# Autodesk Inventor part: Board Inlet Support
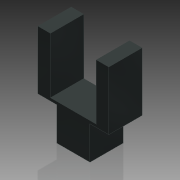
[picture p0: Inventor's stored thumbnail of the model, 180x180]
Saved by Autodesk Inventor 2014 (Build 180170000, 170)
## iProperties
Created: 2015-07
Part Number: Board Inlet Support
Material: Generic
Document SubType Name: Modeling
Designer: Brad Factor
Density: 1 g/cm^3
Appearance: Gunmetal - Polished
Author: Brad Factor
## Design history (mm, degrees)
sketch "Sketch1"
  geometry: L1 (-4.382, 11.176)-(-4.382, 0.533); L2 (-4.382, 0.533)-(4.382, 0.533); L3 (4.382, 0.533)-(4.382, 11.176); L4 (4.382, 11.176)-(6.763, 11.176); L5 (6.763, 11.176)-(6.763, 0); L6 (6.763, 0)-(3.175, 0); L7 (3.175, 0)-(3.175, -6.35); L8 (3.175, -6.35)-(-3.175, -6.35); L9 (-3.175, -6.35)-(-3.175, 0); L10 (-3.175, 0)-(-6.763, 0); L11 (-6.763, 0)-(-6.763, 11.176); L12 (-6.763, 11.176)-(-4.382, 11.176); 3 further points
  constraints: 24 end point, 6 horizontal, 6 vertical, 2 horizontal alignment, 2 midpoint, 2 vertical alignment, 1 collinear
  dimensions: "d0" = 8.763 distance of L1.end L2.end; "d1" = 11.176 distance of L10.end L11.end; "d2" = 2.38125 distance of L11.end L1.start; "d3" = 2.38125 distance between parallel lines of L3 L5; "d4" = 6.35 distance of L7.end L8.end; "d5" = 0.5334 distance between parallel lines of L2 L6; "d6" = 6.35 distance of L8.end L9.end
extrude "Base" new body sketch "Sketch1" distance "d7" = 6.35; taper "d8" = 0 deg
body "Solid1"
